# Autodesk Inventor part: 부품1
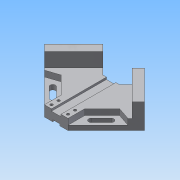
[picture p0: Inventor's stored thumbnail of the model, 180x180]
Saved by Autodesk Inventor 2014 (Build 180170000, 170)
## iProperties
Created: 2019-04
Part Number: 부품1
Material: 알루미늄 6061
Document SubType Name: Modeling
Designer: net
Density: 2.71 g/cm^3
Appearance: 알루미늄 - 평지
Mass: 603.503 g
Surface Area: 425.555 cm^2
Volume: 222.695 cm^3
Author: net
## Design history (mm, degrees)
sketch "스케치2"
  geometry: L1 (0, 84.853)-(-84.853, 0); L2 (-84.853, 0)-(0, -84.853); L3 (0, -84.853)-(84.853, 0); L4 (84.853, 0)-(0, 84.853); L5 (0, 84.853)-(0, -84.853); L6 (-84.853, 0)-(84.853, 0); 2 further points
  constraints: 12 end point, 3 midpoint, 2 parallel, 1 perpendicular, 1 vertical alignment
  dimensions: "d3" = 120 distance between parallel lines of L3 L1; "d4" = 120 distance between parallel lines of L2 L4
extrude "돌출1" new body sketch "스케치2" distance "d5" = 42; taper "d6" = 0 deg
sketch "스케치4"
  geometry: L1 (-84.853, 0)-(0, -84.853) reference; L2 (0, -84.853)-(84.853, 0) reference; L3 (-20, -64.853)-(20, -64.853); 1 further point
  constraints: 2 end point, 2 point on line, 1 horizontal
  dimensions: "d9" = 20 distance from line of L1.end L3
extrude "돌출2" cut sketch "스케치4" distance "d10" = 42; taper "d11" = 0 deg
sketch "스케치5"
  geometry: L1 (-20, -64.853)-(20, -64.853) reference; L2 (20, -64.853)-(84.853, 0) reference; L3 (84.853, 0)-(0, 84.853) reference; L4 (0, 84.853)-(-84.853, 0) reference; L5 (-84.853, 0)-(-20, -64.853) reference; L6 (74.246, -10.607)-(0, 63.64); L7 (-74.246, -10.607)-(0, 63.64); 1 further point
  constraints: 4 end point, 2 perpendicular, 2 point on line
  dimensions: "d12" = 15 distance between parallel lines of L3 L6; "d13" = 15 distance between parallel lines of L7 L4
extrude "돌출3" cut sketch "스케치5" distance "d14" = 24; taper "d15" = 0 deg
sketch "스케치6"
  geometry: L1 (84.853, 0)-(0, 84.853) reference; L2 (0, 84.853)-(-84.853, 0) reference; L3 (20, -64.853)-(-20, -64.853) reference; L4 (74.246, -10.607)-(20, -64.853) reference; L5 (0, 63.64)-(74.246, -10.607) reference; L6 (-74.246, -10.607)-(0, 63.64) reference; L7 (-20, -64.853)-(-74.246, -10.607) reference; L8 (-35.355, 49.497)-(-14.005, 28.147); L9 (-14.005, 28.147)-(14.005, 28.147); L10 (14.005, 28.147)-(35.355, 49.497); 1 further point
  constraints: 6 end point, 2 parallel, 2 point on line, 1 perpendicular
  dimensions: "d16" = 50 distance between parallel lines of L2 L10; "d17" = 50 distance between parallel lines of L8 L1; "d18" = 93 distance between parallel lines of L3 L9
extrude "돌출4" cut sketch "스케치6" distance "d19" = 50; taper "d20" = 0 deg
sketch "스케치7"
  geometry: L1 (14.005, 28.147)-(-14.005, 28.147) reference; L2 (20, -64.853)-(-20, -64.853) reference; L3 (-8, 28.147)-(-8, -64.853); L4 (8, 28.147)-(8, -64.853); 1 further point
  constraints: 4 end point, 4 point on line, 1 parallel, 1 perpendicular
  dimensions: "d21" = 16 distance between parallel lines of L3 L4; "d22" = 8 distance from line of point (0, 0) L3
extrude "돌출5" cut sketch "스케치7" distance "d23" = 3.5; taper "d24" = 0 deg
sketch "스케치8"
  geometry: L1 (-20, -64.853)-(20, -64.853) reference; L2 (14.005, 28.147)-(-14.005, 28.147) reference; L3 (-6, 28.147)-(-6, -64.853); L4 (6, 28.147)-(6, -64.853); 1 further point
  constraints: 4 end point, 4 point on line, 2 perpendicular
  dimensions: "d25" = 12 distance between parallel lines of L4 L3; "d26" = 6 distance from line of point (0, 0) L3
extrude "돌출6" cut sketch "스케치8" distance "d27" = 3; taper "d28" = 0 deg
sketch "스케치11"
  geometry: L1 (6, -64.853)-(-6, -64.853) reference; C1 r 4 at (-14, -58.853); C2 r 4 at (-14, -46.853); 1 further point
  constraints: 2 centre point, 1 vertical alignment
  dimensions: "d39" = 6 distance from line of L1 C1.centre; "d40" = 12 distance of C2.centre C1.centre; "d41" = 14 horizontal distance of point (0, 0) C1.centre; "d42" = 8 diameter of C1; "d43" = 8 diameter of C2
extrude "돌출8" cut sketch "스케치11" distance "d44" = 10; taper "d45" = 0 deg
sketch "스케치12"
  geometry: L1 (8, -64.853)-(-8, -64.853) reference; C1 r 2.25 at (14, -46.853); C2 r 2.25 at (14, -58.853); 1 further point
  constraints: 2 centre point, 1 vertical alignment
  dimensions: "d46" = 14 horizontal distance of point (0, 0) C1.centre; "d47" = 12 distance of C2.centre C1.centre; "d48" = 4.5 diameter of C1; "d49" = 4.5 diameter of C2; "d50" = 6 distance from line of L1 C2.centre
extrude "돌출9" cut sketch "스케치12" distance "d51" = 20; taper "d52" = 0 deg
sketch "스케치14"
  geometry: L1 (-35.355, 49.497)-(-84.853, 0) reference; L2 (70.711, -14.142)-(49.497, -7.071); L3 (49.497, -7.071)-(20, -36.569); L4 (8, 28.147)-(8, -64.853) reference; L5 (20, -64.853)-(8, -64.853) reference; L6 (74.246, -10.607)-(20, -64.853) reference; L7 (24.749, 38.891)-(74.246, -10.607) reference; L8 (24.749, 38.891)-(14.005, 28.147) reference; L9 (14.005, 28.147)-(8, 28.147) reference; L10 (84.853, 0)-(35.355, 49.497) reference; L11 (35.355, 49.497)-(24.749, 38.891) reference; L12 (24.749, 38.891)-(74.246, -10.607) reference; L13 (74.246, -10.607)-(84.853, 0) reference; L14 (84.853, 0)-(35.355, 49.497) reference; L15 (74.246, -10.607)-(20, -64.853) reference; L16 (20, -36.569)-(20, -64.853); C1 r 2.25 at (14, -46.853) reference; C2 r 2.25 at (14, -58.853) reference; 1 further point
  constraints: 6 end point, 2 point on line, 1 parallel, 1 perpendicular
  dimensions: "d56" = 20 distance between parallel lines of L6 L3; "d57" = 20 distance from line of L2.start L10; "d58" = 30 distance from line of L10 L2.end; "d63" = 20 distance from line of point (0, 0) L16
extrude "돌출10" cut sketch "스케치14" distance "d64" = 10; taper "d65" = 0 deg
sketch "스케치15"
  geometry: L1 (70.711, -14.142)-(20, -64.853) reference; L2 (49.497, -21.213)-(32.527, -38.184); L3 (46.315, -18.031)-(29.345, -35.002); L4 (35.709, -41.366)-(52.679, -24.395); L5 (-49.497, -7.071)-(-20, -36.569) reference; L6 (-20, -36.569)-(-20, -64.853) reference; L7 (-8, -64.853)-(-20, -64.853) reference; L8 (-8, -64.853)-(-8, 28.147) reference; L9 (-8, 28.147)-(-14.005, 28.147) reference; L10 (-14.005, 28.147)-(-24.749, 38.891) reference; L11 (-74.246, -10.607)-(-24.749, 38.891) reference; L12 (-70.711, -14.142)-(-74.246, -10.607) reference; L13 (-70.711, -14.142)-(-49.497, -7.071) reference; L14 (-49.497, -7.071)-(-20, -36.569) reference; L15 (-20, -64.853)-(-70.711, -14.142) reference; L16 (84.853, 0)-(35.355, 49.497) reference; C1 r 2.25 at (-14, -46.853) reference; C2 r 2.25 at (-14, -58.853) reference; A1 r 4.5 centre (49.497, -21.213) between (52.679, -24.395) and (46.315, -18.031); A2 r 4.5 centre (32.527, -38.184) between (29.345, -35.002) and (35.709, -41.366); 2 further points
  constraints: 8 end point, 4 point on circle, 4 tangent, 2 centre point, 2 parallel, 1 midpoint
  dimensions: "d66" = 10 distance from line of L1 L2.start; "d67" = 40 distance from line of L16 L2.start; "d70" = 9 distance between parallel lines of L3 L4; "d72" = 24 distance of L2.start L2.end
extrude "돌출11" cut sketch "스케치15" distance "d73" = 50; taper "d74" = 0 deg
node "솔리드1"
mirror "대칭1"
mirror "대칭2"
mirror "대칭3"
mirror "대칭4"
node "투영된 루프1"
node "투영된 루프2"
node "투영된 루프3"
node "투영된 루프4"
